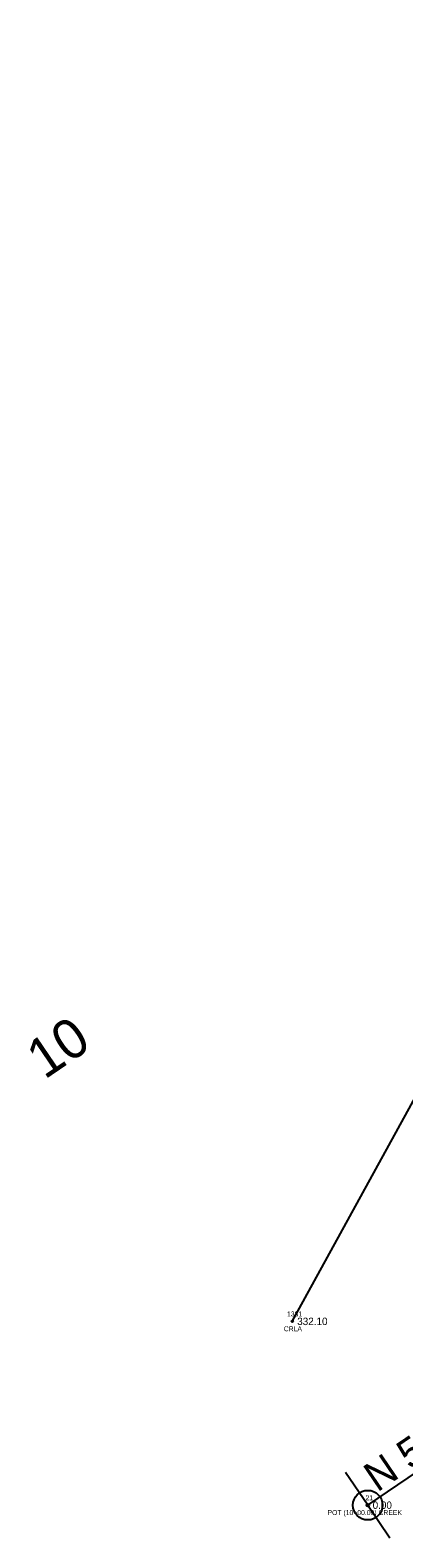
# Model space of a CAD drawing. Extents: x 2006517 to 2008868, y 1001613 to 1004633.
# Drawn here: x 2007231.2 to 2007306.9, y 1002980.7 to 1003286 of the extents above; entities that cross this region are included whole.
import ezdxf

# ---------------------------------------------------------------- set-up
doc = ezdxf.new("R2010")
doc.units = 0
for name, color, linetype in [('RD_EX_H2O', 7, 'Continuous'), ('RD_EX_H2O_txCode', 7, 'Continuous'), ('RD_EX_TX_H2O_ELEV', 7, 'Continuous'), ('RD_HC_Cl', 7, 'Continuous'), ('RD_HC_Data', 7, 'Continuous'), ('RD_HC_Data_Tic', 7, 'Continuous'), ('RD_HC_Survey_ELEV', 7, 'Continuous'), ('RD_HC_TX_Sta50', 7, 'Continuous'), ('RD_HC_txCode', 7, 'Continuous'), ('RD_SMD_Locator', 7, 'Continuous')]:
    doc.layers.add(name, color=color, linetype=linetype)

msp = doc.modelspace()

# ---------------------------------------------------------------- linework, layer by layer
at = {"layer": 'RD_EX_H2O'}
msp.add_lwpolyline([(2007284.3, 1003024.58), (2007315.57, 1003081.44), (2007361.06, 1003122.03), (2007422.5, 1003146.8), (2007480.38, 1003127.6), (2007536.49, 1003104.06), (2007552.28, 1003095.79)], dxfattribs=at)
at = {"layer": 'RD_HC_Cl'}
msp.add_line((2007299.58, 1002987.36), (2007350.64, 1003022.03), dxfattribs=at)
msp.add_arc((2008085.61, 1003809.27), 810.87, 194.53337, 229.57273, dxfattribs=at)
at = {"layer": 'RD_HC_Data'}
for radius in [3, 0.282]:
    msp.add_circle((2007299.58, 1002987.36), radius, dxfattribs=at)
at = {"layer": 'RD_HC_Data_Tic'}
for q in [(2007295.08, 1002993.98), (2007304.07, 1002980.74)]:
    msp.add_line((2007299.58, 1002987.36), q, dxfattribs=at)
at = {"layer": 'RD_SMD_Locator'}
for centre in [(2007284.3, 1003024.58), (2007299.58, 1002987.36)]:
    msp.add_circle(centre, 0.15, dxfattribs=at)

# ---------------------------------------------------------------- texts
at = {"layer": 'RD_EX_H2O_txCode'}
for s, p in [('1381', (2007283.23, 1003025.58)), ('CRLA', (2007282.58, 1003022.58))]:
    msp.add_text(s, height=1, dxfattribs=at).set_placement(p)
at = {"layer": 'RD_EX_TX_H2O_ELEV'}
msp.add_text('332.10', height=1.5, dxfattribs=at).set_placement((2007285.3, 1003023.83))
at = {"layer": 'RD_HC_Data'}
msp.add_text('N 55%%d 49\' 17" E', height=6, rotation=34.1786, dxfattribs=at).set_placement((2007301.51, 1002989.88))
at = {"layer": 'RD_HC_Survey_ELEV'}
msp.add_text('0.00', height=1.5, dxfattribs=at).set_placement((2007300.58, 1002986.61))
at = {"layer": 'RD_HC_TX_Sta50'}
msp.add_text('10', height=8, rotation=34.1786, dxfattribs=at).set_placement((2007234.11, 1003073.45))
at = {"layer": 'RD_HC_txCode'}
for s, p in [('21', (2007299.13, 1002988.36)), ('POT (10+00.00) CREEK', (2007291.44, 1002985.36))]:
    msp.add_text(s, height=1, dxfattribs=at).set_placement(p)

doc.saveas('drawing.dxf')
